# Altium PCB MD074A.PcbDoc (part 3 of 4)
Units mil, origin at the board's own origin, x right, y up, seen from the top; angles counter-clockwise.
Board outline 3224.41 x 4078.74 mil, 4 copper layers (Top Layer, Signal Layer 1, Signal Layer 2, Bottom Layer), stack 61.2 mil thick; 217 components, 121 nets, 624 pads, 901 vias.
Unrouted connection lines stored in the file: 116.
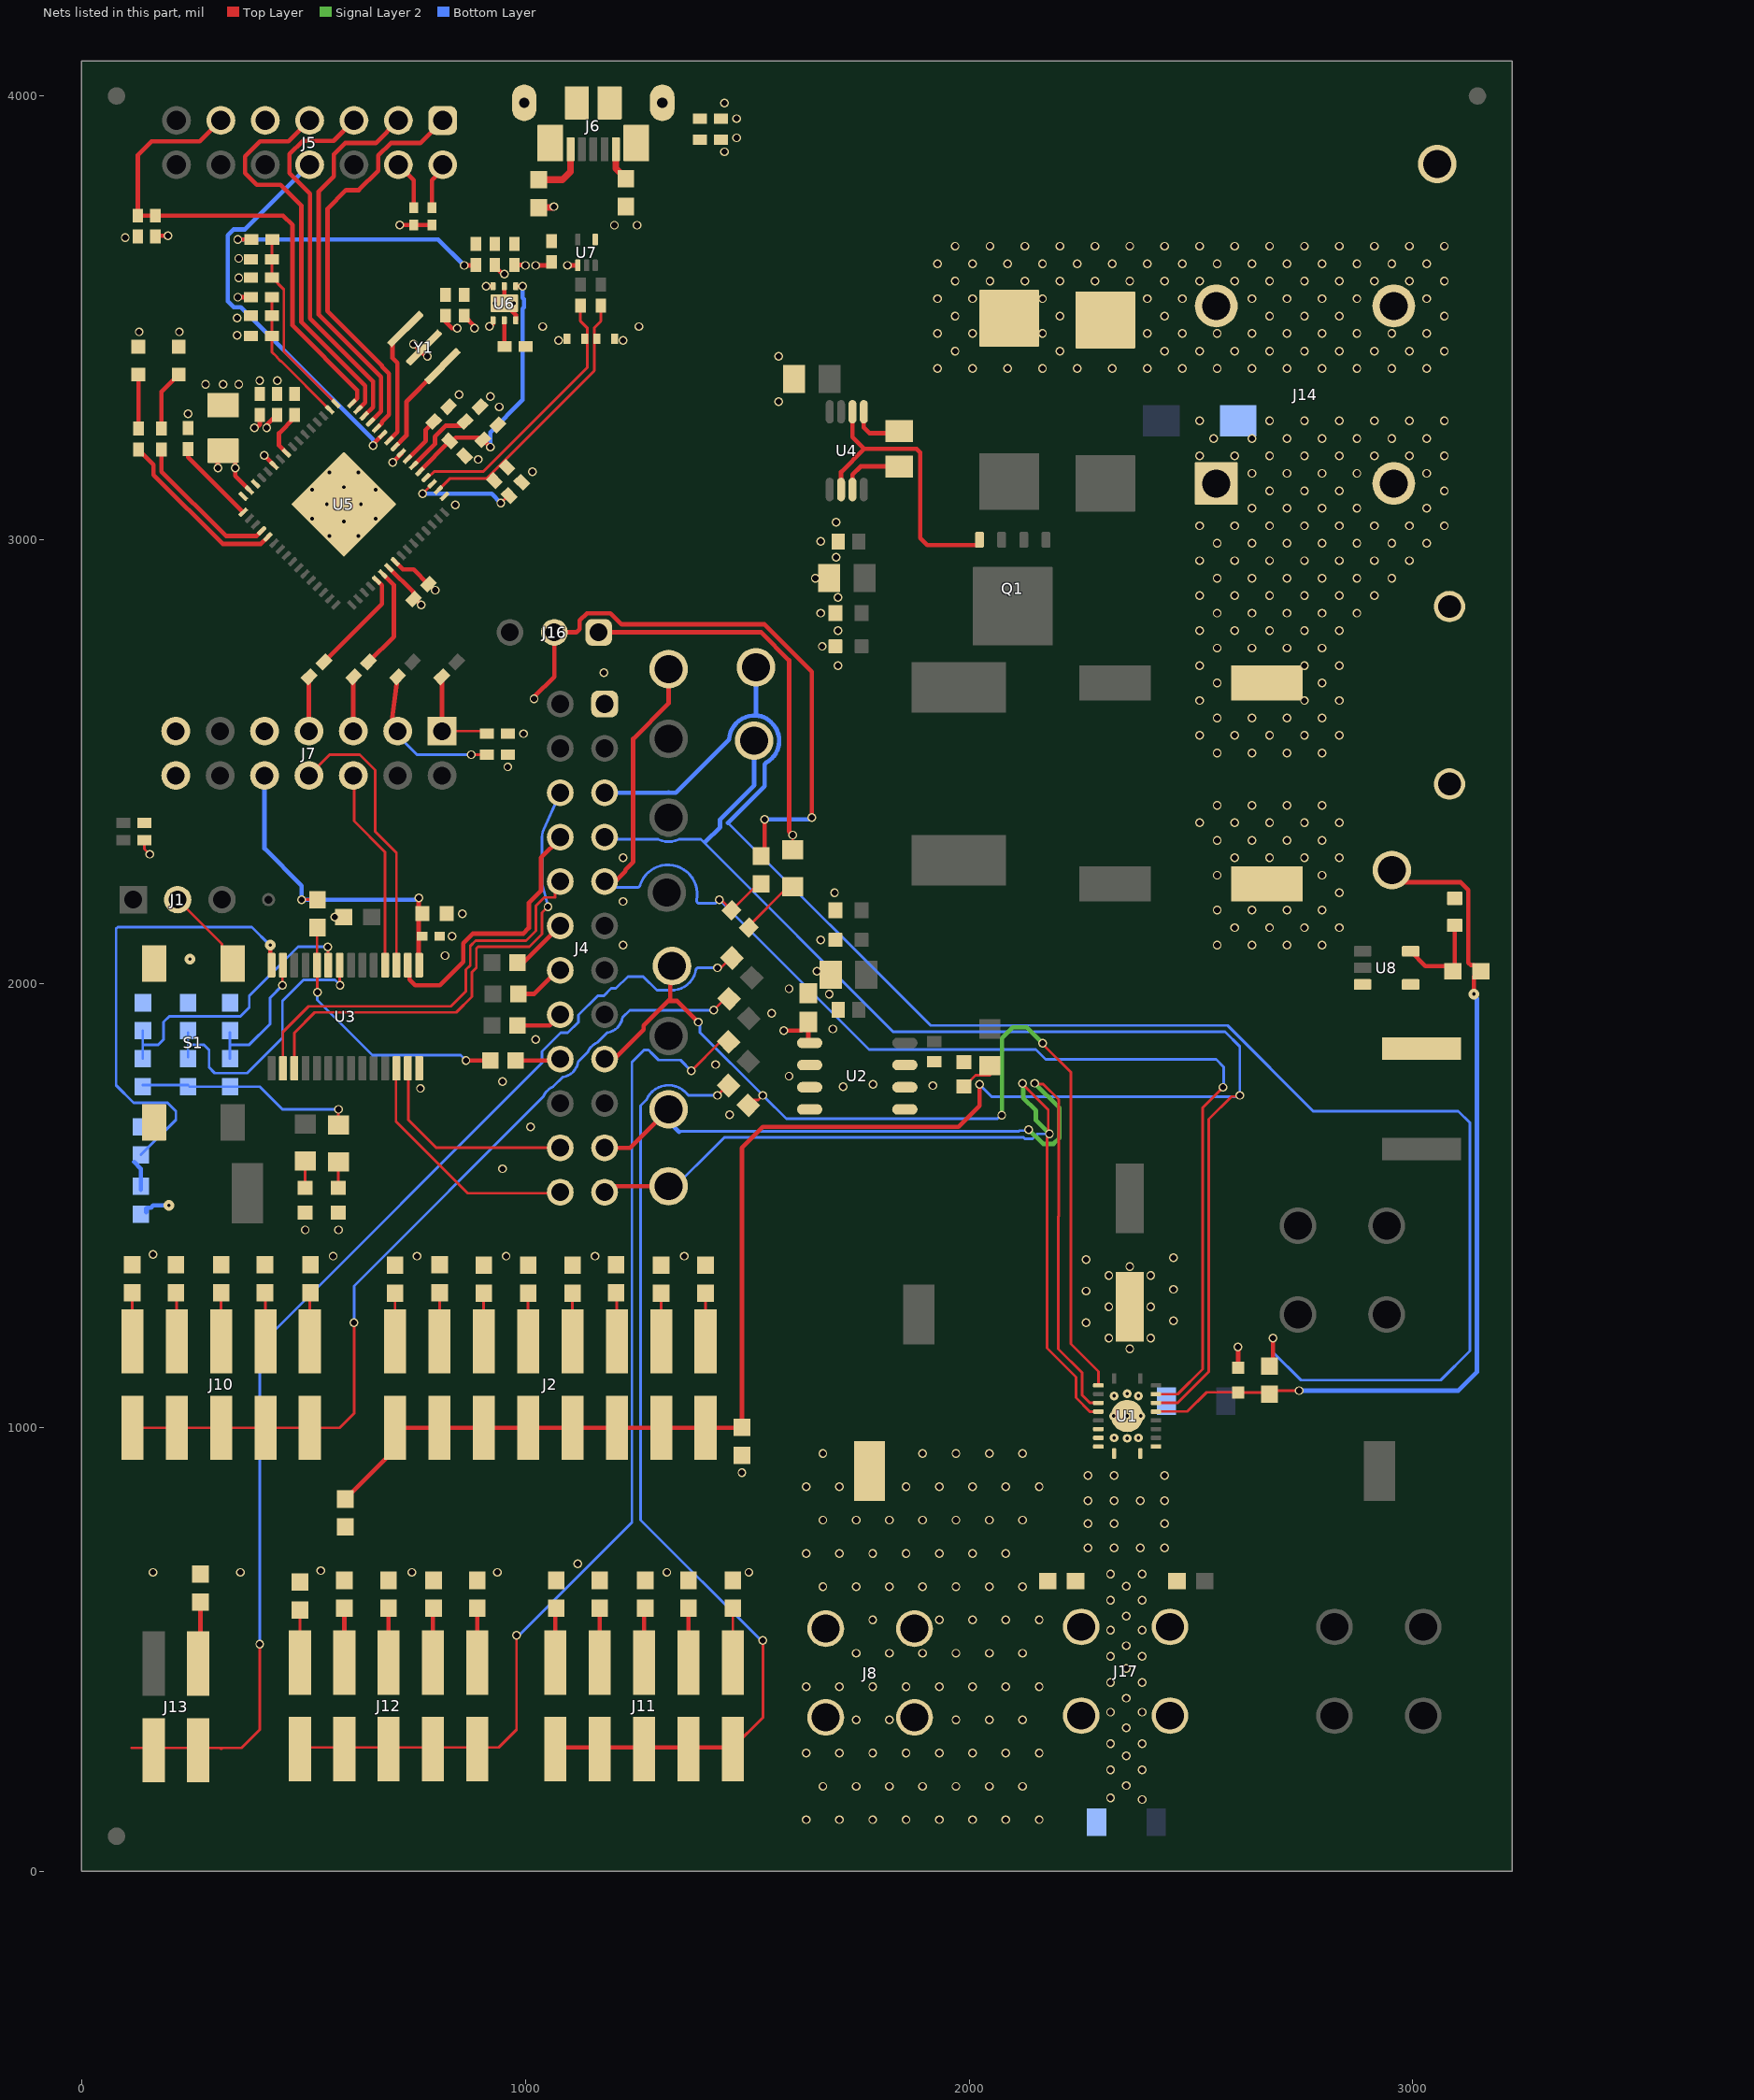
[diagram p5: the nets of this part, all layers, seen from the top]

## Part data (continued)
J3 J8 J9: library part CMP-0055418-2, "Banana Jack Insul Nylon Red, R/A, TH", Color=Red, Current_A=25A, Manufacturer="Cal Test Electronics", Supplier Part Number 1=BKCT3151SP-2-ND, Voltage_V=1kV
J4: library part CMP-0085938-1, "Header, 2.54mm, 12x2, Gold, TH", Alternate Manufacturer="Wurth Elektronik", Alternate PartNumber=61302421121, Color=Black, Current_A=5A, Manufacturer=FCI, Voltage_V=1.5kV
J5: library part CMP-0086014-1, "Header, 2.54mm, 7x2, Gold, TH", Color=Black, Current_A=3A, Manufacturer="Wurth Elektronik", Voltage_V=250V
J6: "Receptacle, USB 2.0, Micro B, 5 Position, R/A, SMT", Color=Black, Current_A=1.8A, Manufacturer=Molex, PartNumber=1051640001, Supplier Part Number 1=WM11263CT-ND, Voltage_V=30V
J7: library part CMP-0002339-2, "Header, 100mil, 7x2, Tin, TH", Alternate Manufacturer="Wurth Elektronik", Alternate PartNumber=61301421121, Color=Black, Current_A=3A, Manufacturer="Sullins Connector Solutions", Supplier Part Number 1=S2012E-07-ND, Voltage_V=1.8kV
J10 J11 J12: library part CMP-0055598-2, "Header, 2.54mm, 5x2, Gold, SMT", Alternate Manufacturer="Wurth Elektronik", Alternate PartNumber=61031021121, Color=Black, Current_A=5.4A, Manufacturer=Samtec, Supplier Part Number 1=SAM8741-ND, Voltage_V=475V
J13: library part CMP-0055559-1, "Header, 2.54mm, 2x2, Gold, SMT", Color=Black, Manufacturer=Samtec, Supplier Part Number 1=TSM-102-01-L-DV-ND, Voltage_V=475V
J14: library part CMP-0086764-1, Current_A=57A, Manufacturer=Wurth, Voltage_V=750V
J15: library part CMP-0075110-1, "1mm Uninsulated Shorting Plug, 10.16mm spacing, TH", Manufacturer=Harwin, Supplier Part Number 1=952-1873-ND
J16: library part CMP-0079327-1, "Header, 2.54mm, 3x1, Gold, TH", Alternate Manufacturer="Wurth Elektronik", Alternate PartNumber=61300311121, Color=Black, Manufacturer=Samtec, Supplier Part Number 1=SAM1038-03-ND
J17: library part CMP-0055417-1, "Banana Jack Insul Nylon Black, R/A, TH", Color=Black, Current_A=25A, Manufacturer="Cal Test Electronics", Supplier Part Number 1=BKCT3151SP-0-ND, Voltage_V=1kV
L1: library part CMP-0063986-1, "Inductor, Shielded Drum Core, Ferrite, 1 uH, 24 A, 0.0012 ohm, SMD", Manufacturer="Wurth Elektronik", Supplier Part Number 1=732-2138-1-ND, Value1="0.0012 ohm", Value2=24A, ValueDisplayed=1uH
L2 L3: library part CMP-0081962-1, "Ferrite Bead, 150 ohm @ 100 MHz, 0.7 A, 0603", Manufacturer=MuRata, Supplier Part Number 1=490-14035-1-ND, Value1="0.35 ohm", Value2=0.7A, ValueDisplayed="150 ohm"
LBL1: library part CMP-0003625-1, "Thermal Transfer Printable Labels, 0.650\" W x 0.200\" H - 10,000 per roll", Manufacturer=Brady, Supplier Part Number 1=97C5133
Logo1: library part CMP-0074844-1
Logo2: library part CMP-0074838-1, "Texas Instrument Corporate Signature"
Logo3: library part CMP-0074847-1, "FCC_disclaimer"
Logo4: library part CMP-0074769-1
Logo5: library part CMP-0074836-1, "IEC 61010-1 Caution Warning"
LOGO6: library part CMP-0074837-2, "IEC 61010-1 Hot Surface Warning", Manufacturer="Texas Instruments"
Q1: library part CMP-0000714-1, "MOSFET, N-CH, 40 V, 100 A, DQJ0008A (VSONP-8)", Alternate Manufacturer=None, Manufacturer="Texas Instruments", Supplier Part Number 1=296-45231-1-ND, Value1=0.004, Value2="47 nC"
R1 R68: library part CMP-0025886-3, "RES, 10 k, 5%, 0.1 W, 0603", Manufacturer="Yageo America", Power_W=100mW, Supplier Part Number 1=311-10KGRCT-ND, TempCo="100 ppm/C", Tolerance_%=5%, Value2=0.1W, Value_Code=10k0, ValueDisplayed=10k
R2 R3 R20: "RES, 330, 5%, 0.1 W, AEC-Q200 Grade 0, 0603", Manufacturer=Vishay-Dale, PartNumber=CRCW0603330RJNEA, Power_W=100mW, Supplier Part Number 1=541-330GCT-ND, TempCo="200 ppm/C", Tolerance_%=5%, Value2=0.1W, Value_Code=330R, ValueDisplayed=330
R4: library part CMP-0082533-1, "RES, 4.99 k, 1%, 0.1 W, 0603", Manufacturer=Vishay-Dale, Power_W=100mW, Supplier Part Number 1=541-3985-1-ND, TempCo="100 ppm/C", Tolerance_%=1%, Value2=0.1W, Value_Code=4k99, ValueDisplayed=4.99k
R5: library part CMP-0023235-5, "RES, 680, 1%, 0.1 W, 0603", Manufacturer=Yageo, Power_W=100mW, Supplier Part Number 1=311-680HRCT-ND, TempCo="100 ppm/C", Tolerance_%=1%, Value2=0.1W, Value_Code=680R, ValueDisplayed=680
R6: library part CMP-0022895-5, "RES, 1.00 k, 1%, 0.1 W, 0603", Manufacturer=Yageo, Power_W=100mW, Supplier Part Number 1=311-1.00KHRCT-ND, TempCo="100 ppm/C", Tolerance_%=1%, Value2=0.1W, Value_Code=1k00, ValueDisplayed=1.00k
R7: library part CMP-0022883-5, "RES, 1.50 k, 1%, 0.1 W, 0603", Manufacturer=Yageo, Power_W=100mW, Supplier Part Number 1=311-1.50KHRCT-ND, TempCo="100 ppm/C", Tolerance_%=1%, Value2=0.1W, Value_Code=1k50, ValueDisplayed=1.50k
R8: library part CMP-0022986-5, "RES, 2.20 k, 1%, 0.1 W, 0603", Manufacturer=Yageo, Power_W=100mW, Supplier Part Number 1=311-2.20KHRCT-ND, TempCo="100 ppm/C", Tolerance_%=1%, Value2=0.1W, Value_Code=2k20, ValueDisplayed=2.20k
R9: library part CMP-0023081-5, "RES, 3.30 k, 1%, 0.1 W, 0603", Manufacturer=Yageo, Power_W=100mW, Supplier Part Number 1=311-3.30KHRCT-ND, TempCo="100 ppm/C", Tolerance_%=1%, Value2=0.1W, Value_Code=3k30, ValueDisplayed=3.30k
R10: library part CMP-0023153-5, "RES, 4.70 k, 1%, 0.1 W, 0603", Manufacturer=Yageo, Power_W=100mW, Supplier Part Number 1=311-4.70KHRCT-ND, TempCo="100 ppm/C", Tolerance_%=1%, Value2=0.1W, Value_Code=4k70, ValueDisplayed=4.70k
R11: library part CMP-0023253-5, "RES, 6.80 k, 1%, 0.1 W, 0603", Manufacturer=Yageo, Power_W=100mW, Supplier Part Number 1=311-6.80KHRCT-ND, TempCo="100 ppm/C", Tolerance_%=1%, Value2=0.1W, Value_Code=6k80, ValueDisplayed=6.80k
R12 R53 R54 R55: library part CMP-0025862-3, "RES, 8.2 k, 5%, 0.1 W, 0603", Manufacturer=Vishay-Dale, Power_W=100mW, Supplier Part Number 1=541-8.2KGCT-ND, TempCo="200 ppm/C", Tolerance_%=5%, Value2=0.1W, Value_Code=8k20, ValueDisplayed=8.2k
R13 R14 R15 R16 R17 R19 R22 R23 R39 R52: library part CMP-0086358-1, "RES, 0, 0%, 0.25 W, AEC-Q200 Grade 0, 0603", Manufacturer=Rohm, Power_W=250mW, Tolerance_%=0%, Value2=0.25W, Value_Code=0000, ValueDisplayed=0
R18: library part CMP-0025925-5, "RES, 47 k, 5%, 0.1 W, 0603", Manufacturer=Yageo, Power_W=100mW, Supplier Part Number 1=311-47KGRCT-ND, TempCo="100 ppm/C", Tolerance_%=5%, Value2=0.1W, Value_Code=47k0, ValueDisplayed=47k
R21 R24 R29 R67 R69 R70 R71 R72: library part CMP-0025886-5, "RES, 10 k, 5%, 0.1 W, 0603", Manufacturer=Yageo, Power_W=100mW, Supplier Part Number 1=311-10KGRCT-ND, TempCo="100 ppm/C", Tolerance_%=5%, Value2=0.1W, Value_Code=10k0, ValueDisplayed=10k
R25 R26 R27 R28: library part CMP-2000-03817-1, Manufacturer="Vishay Dale"
R32: library part CMP-0026190-2, "RES, 240 k, 1%, 0.063 W, AEC-Q200 Grade 0, 0402", Manufacturer=Vishay-Dale, Power_W=63mW, Supplier Part Number 1=541-240KLCT-ND, TempCo="100 ppm/C", Tolerance_%=1%, Value2=0.063W, Value_Code=240k
R33: library part CMP-0026934-3, "RES, 470, 5%, 0.063 W, AEC-Q200 Grade 0, 0402", Manufacturer=Vishay-Dale, Power_W=63mW, Supplier Part Number 1=541-470JCT-ND, TempCo="200 ppm/C", Tolerance_%=5%, Value2=0.063W, Value_Code=470R, ValueDisplayed=470
R34: library part CMP-0026914-3, "RES, 390, 5%, 0.063 W, AEC-Q200 Grade 0, 0402", Manufacturer=Vishay-Dale, Power_W=63mW, Supplier Part Number 1=541-390JCT-ND, TempCo="200 ppm/C", Tolerance_%=5%, Value2=0.063W, Value_Code=390R, ValueDisplayed=390
R35: library part CMP-0026021-3, "RES, 150 k, 1%, 0.063 W, AEC-Q200 Grade 0, 0402", Manufacturer=Vishay-Dale, Power_W=63mW, Supplier Part Number 1=541-150KLCT-ND, TempCo="100 ppm/C", Tolerance_%=1%, Value2=0.063W, Value_Code=150k
R36 R38: library part CMP-0026728-1, "RES, 220 k, 1%, 0.0625 W, 0402", Manufacturer="Yageo America", Power_W=62.5mW, Supplier Part Number 1=311-220KLRCT-ND, TempCo="100 ppm/C", Tolerance_%=1%, Value2=0.0625W, Value_Code=220k
R37 R73: library part CMP-0026935-3, "RES, 47 k, 5%, 0.063 W, AEC-Q200 Grade 0, 0402", Manufacturer=Vishay-Dale, Power_W=63mW, Supplier Part Number 1=541-47KJCT-ND, TempCo="200 ppm/C", Tolerance_%=5%, Value2=0.063W, Value_Code=47k0, ValueDisplayed=47k
R41 R42: library part CMP-0026992-3, "RES, 0, 5%, 0.1 W, AEC-Q200 Grade 0, 0402", Manufacturer=Panasonic, Power_W=100mW, Supplier Part Number 1=P0.0JCT-ND, TempCo="600 ppm/C", Tolerance_%=5%, Value2=0.1W, Value_Code=0000, ValueDisplayed=0
R43 R44: library part CMP-0026888-3, "RES, 27, 5%, 0.063 W, AEC-Q200 Grade 0, 0402", Manufacturer=Vishay-Dale, Power_W=63mW, Supplier Part Number 1=541-27JCT-ND, TempCo="200 ppm/C", Tolerance_%=5%, Value2=0.063W, Value_Code=27R0, ValueDisplayed=27
R45: library part CMP-0026085-3, "RES, 1.40 k, 1%, 0.063 W, AEC-Q200 Grade 0, 0402", Manufacturer=Vishay-Dale, Power_W=63mW, Supplier Part Number 1=541-1.40KLCT-ND, TempCo="100 ppm/C", Tolerance_%=1%, Value2=0.063W, Value_Code=1k40, ValueDisplayed=1.40k
R46: library part CMP-0026859-2, "RES, 1.0 M, 5%, 0.063 W, AEC-Q200 Grade 0, 0402", Manufacturer=Vishay-Dale, Power_W=63mW, Supplier Part Number 1=541-1.0MJCT-ND, TempCo="200 ppm/C", Tolerance_%=5%, Value2=0.063W, Value_Code=1M00, ValueDisplayed=1.0M
R47: library part CMP-0025963-2, "RES, 10.0, 1%, 0.063 W, 0402", Alternate Manufacturer="Wurth Elektronik", Alternate PartNumber=560050310009, Manufacturer=Vishay-Dale, Power_W=63mW, Supplier Part Number 1=541-10.0LCT-ND, TempCo="100 ppm/C", Tolerance_%=1%, Value2=0.063W, Value_Code=10R0, ValueDisplayed=10.0
R48 R49 R50: library part CMP-0025963-2, "RES, 10.0, 1%, 0.063 W, 0402", Manufacturer=Vishay-Dale, Power_W=63mW, Supplier Part Number 1=541-10.0LCT-ND, TempCo="100 ppm/C", Tolerance_%=1%, Value2=0.063W, Value_Code=10R0, ValueDisplayed=10.0
R51: library part CMP-0026907-3, "RES, 33 k, 5%, 0.063 W, AEC-Q200 Grade 0, 0402", Manufacturer=Vishay-Dale, Power_W=63mW, Supplier Part Number 1=541-33KJCT-ND, TempCo="200 ppm/C", Tolerance_%=5%, Value2=0.063W, Value_Code=33k0, ValueDisplayed=33k
R57 R58 R59: library part CMP-0025757-4, "RES, 22 k, 5%, 0.1 W, AEC-Q200 Grade 0, 0603", Manufacturer=Vishay-Dale, Power_W=100mW, Supplier Part Number 1=541-22KGCT-ND, TempCo="200 ppm/C", Tolerance_%=5%, Value2=0.1W, Value_Code=22k0, ValueDisplayed=22k
R61 R62 R63: library part CMP-0022438-1, "RES, 47.0 k, 1%, 0.1 W, AEC-Q200 Grade 0, 0603", Manufacturer=Vishay-Dale, Power_W=100mW, Supplier Part Number 1=541-47.0KHCT-ND, TempCo="100 ppm/C", Tolerance_%=1%, Value2=0.1W, Value_Code=47k0, ValueDisplayed=47.0k
R64 R65 R66: library part CMP-0086261-1, "RES, 100 k, 0.5%, 0.1 W, AEC-Q200 Grade 0, 0603", Manufacturer=Vishay-Dale, Power_W=100mW, TempCo="50 ppm/C", Tolerance_%=0.5%, Value2=0.1W, Value_Code=100k
S1: library part CMP-0002134-3, "Switch, Tactile, SPST-NO, 0.05A, 12V, SMT", CurrentRating_mA=50A, Manufacturer="TE Connectivity", Supplier Part Number 1=450-1129-ND
SH-J1 SH-J2 SH-J3 SH-J4 SH-J5 SH-J6 SH-J7 SH-J8 SH-J9 SH-J10 SH-J11 SH-J12 SH-J13 SH-J14 SH-J15 SH-J16 SH-J17 SH-J19 SH-J20 SH-J21 SH-J22 SH-J23: library part CMP-0003761-2, "Shunt, 2.54mm, Gold, Black", Manufacturer="Wurth Elektronik", Supplier Part Number 1=732-2678-ND
TP1 TP2 TP5 TP6: library part CMP-0055152-1, "Test Point, Miniature, SMT", Manufacturer=Keystone, Supplier Part Number 1=36-5015TR-ND
TP3: library part CMP-0003719-1, "Testpoint", Manufacturer="Texas Instruments"
TP4 TP7 TP8 TP10 TP11 TP12 TP13 TP14 TP15 TP16 TP17: library part CMP-0055147-1, "Test Point, Multipurpose, Red, TH", Color=Red, Manufacturer=Keystone, Supplier Part Number 1=36-5010-ND
TP18: library part CMP-0055147-2, "Test Point, Multipurpose, Red, TH", Color=Red, Manufacturer="Keystone Electronics", Supplier Part Number 1=36-5010-ND
U1: library part CMP-0097829-1, "Automotive H-Bridge Driver with Integrated Current Sense and Diagnostics", Manufacturer="Texas Instruments", Max Supply Voltage=35V, Min Supply Voltage=4.5V, Nominal Supply Current=3mA, Operating Temperature Range="-40°C to +150°C", Switching Frequency=25kHz
U2: library part CMP-0070570-1, "Ultra-Low Quiescent Current Voltage Regulator, 8-pin Narrow SOIC, Pb-Free", Manufacturer="Texas Instruments", PackageTopMarking=NSZXTT*LM903*6M-3, PowerWise=N
U3: library part CMP-0365-00685-2, "16 MHz Mixed Signal Microcontroller with 16 KB Flash, 512 B SRAM and 24 GPIOs, -40 to 85 degC, 28-pin SOP (PW), Green (RoHS & no Sb/Br)", Frequency(MHz)=16, Manufacturer="Texas Instruments", Temp Sensor=Yes
U4: library part CMP-0076397-2, "Zero Iq Reverse Polarity Protection Smart Diode Controller, DGK0008A (VSSOP-8)", Alternate Manufacturer="Texas Instruments"
U5: "16-Bit Ultra-Low-Power Microcontroller, 128KB Flash, 8KB RAM, USB, 12Bit ADC, 2 USCIs, 32Bit HW MPY, RGC0064B (VQFN-64)", Alternate Manufacturer="Texas Instruments", Alternate PartNumber=MSP430F5528IRGCR, Frequency(MHz)=25, Operating Temperature Range="-40 to 85 C", PartNumber=MSP430F5528IRGCT, Rating=Catalog, Temp Sensor=Yes
U6: library part CMP-0036330-5, "Single Output High PSRR LDO, 500 mA, Fixed 3.3 V Output, 2.7 to 6.5 V Input, with Low IQ, 6-pin SON (DRV), -40 to 125 degC, Green (RoHS & no Sb/Br)", Manufacturer="Texas Instruments"
U7: library part CMP-0043096-2, "Low-Capacitance + / - 15 kV ESD-Protection Array for High-Speed Data Interfaces, 2 Channels, -40 to +85 degC, 5-pin SOT (DRL), Green (RoHS & no Sb/Br)", Breakdown Voltage(Min)(V)=11, IO Capacitance(Typ)(pF)=1.5, IO Leakage Current(nA)=1, Manufacturer="Texas Instruments"
U8: library part CMP-0077329-2, "Automotive High-Voltage Ultra-Low IQ Low-Dropout Regulator/Fixed 5-V Output Voltage, DBV0005A (SOT-23-5)", Alternate Manufacturer="Texas Instruments"
Y1: library part CMP-0085483-1, "Oscillator, 4 MHz, 700 ppm, 39 pF, SMD", Frequency_Fixed=4MHz, Frequency Tolerance="700 ppm", Load Capacitance="39 pF", Manufacturer=MuRata
ZZ1: library part CMP-0003616-3
ZZ2: library part CMP-0077236-1
ZZ3: library part CMP-0077237-1
ZZ4: library part CMP-0077238-1

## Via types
v1: diameter 19.68, hole 13.78, Top Layer to Bottom Layer, tented both sides, 869 vias
v2: diameter 19.68, hole 7.87, Top Layer to Bottom Layer, 14 vias
v3: diameter 19.68, hole 7.87, Top Layer to Bottom Layer, tented both sides, 9 vias
v4: diameter 19.68, hole 13.78, Top Layer to Bottom Layer, tented bottom, 5 vias
v5: diameter 24, hole 8, Top Layer to Bottom Layer, tented both sides, 4 vias

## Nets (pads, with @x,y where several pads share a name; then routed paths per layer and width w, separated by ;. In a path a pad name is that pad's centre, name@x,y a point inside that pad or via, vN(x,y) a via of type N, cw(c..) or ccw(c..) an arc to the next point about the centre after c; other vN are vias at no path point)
3V3: C5.1 D2.2 J16.1 U2.1 | length 992.6
  Top Layer w6: D2.2@1602.36,2303.15 v1(1602.36,2334.65)
  Top Layer w10: J16.1@1165.35,2791.34 1531.5,2791.34 1594.49,2728.35 1594.49,2342.52 v1(1602.36,2334.65) ; v1(1582.68,1893.7) 1622.05,1893.7 C5.1@1637.8,1909.45 ; U2.1@1637.8,1866.14 C5.1@1637.8,1909.45 ; C5.1@1637.8,1913.39 C5.1@1637.8,1909.45
3V3_MCU: C17.1 C18.1 D7.2 J7.10 J16.2 R1.2 R18.2 R21.1 R24.1 R67.1 R68.1 R69.1 R73.2 U3.1 | length 2753
  Top Layer w6: R73.2@137.8,2322.83 141.73,2318.9 141.73,2303.15 v1(153.54,2291.34) ; v1(496.06,2188.98) R68.1@531.5,2188.98 ; v1(570.87,2149.61) R18.2@590.55,2149.61 R18.2@602.36,2149.61 ; D7.2@578.74,1681.1 v1(578.74,1716.54) ; R1.2@1527.56,2287.4 R1.2@1531.5,2291.34
  Top Layer w10: U3.1@759.84,2035.43 v1(759.84,2192.91) ; v1@1019.68,2645.67 1065.35,2691.34 J16.2@1065.35,2791.34 1115.02,2791.34 1122.36,2798.68 1122.36,2817.97 1138.72,2834.33 1191.98,2834.33 1217.1,2809.21 1538.9,2809.21 1645.67,2702.44 v4(1645.67,2374.02) ; R1.2@1531.5,2287.4 R1.2@1531.5,2291.34 ; R1.2@1535.43,2291.34 1539.37,2295.28 v4(1539.37,2370.08)
  Bottom Layer w6: R21.1@137.8,1771.65 R67.1@240.16,1771.65 ; R67.1@244.09,1767.72 R69.1@334.65,1767.72 401.57,1767.72 452.76,1716.54 v1(578.74,1716.54)
  Bottom Layer w10: R24.1@145.67,1484.25 145.67,1493.11 147.56,1495 156.42,1495 161.42,1500 v5(196.85,1500) ; J7.10@412.4,2468.8 412.4,2304.14 496.06,2220.47 v1(496.06,2188.98) 751.97,2188.98 v1(759.84,2192.91) ; v4(1539.37,2370.08) 1641.73,2370.08 v4(1645.67,2374.02)
  other v1: 1019.68,2641.73
+5: C40.2 R19.2 U8.5 | length 204.8
  Top Layer w10: U8.5@2995.08,2072.83 3028.54,2039.37 3094.49,2039.37 C40.2@3094.49,2130.91
DRVOFF: J4.23 TP17.1 U1.5 | length 2028.8
  Top Layer w6: v1(2120.65,1774.72) 2120.65,1773.65 2178.48,1715.82 2178.48,1664.04 v1(2181.1,1661.42) 2181.1,1657.71 2175.63,1652.24 2175.63,1178.7 2240.91,1113.43 2240.91,1066.82 2272.3,1035.43 U1.5@2291.34,1035.43
  Top Layer w10: J4.23@1185.04,1531.5 1196.85,1543.31 TP17.1@1322.83,1543.31
  Signal Layer 2 w10: v1(2120.65,1774.72) 2122.05,1773.33 2122.05,1742.11 2150.65,1713.51 2150.65,1691.87 v1(2181.1,1661.42)
  Bottom Layer w6: TP17.1@1318.9,1523.62 1448.82,1653.54 2122.51,1653.54 2125.86,1650.19 2143.02,1650.19 2154.25,1661.42 v1(2181.1,1661.42)
DRVOFF_MCU: J4.24 U3.26 | length 557.4
  Top Layer w6: U3.26@709.65,1809.06 708.66,1808.07 708.66,1688.98 870.08,1527.56 J4.24@1078.74,1527.56
EN/IN1: J4.21 TP16.1 U1.4 | length 2052.1
  Top Layer w6: v1(2148.2,1775.4) 2150.19,1773.41 2167.04,1773.41 2201.82,1738.63 2201.82,1475.54 2201.44,1475.16 2201.44,1176.58 2254.78,1123.24 2254.78,1072.57 2272.03,1055.32 2273.58,1055.32 2273.78,1055.12 U1.4@2291.34,1055.12
  Top Layer w10: J4.21@1192.91,1629.92 1236.22,1629.92 TP16.1@1322.83,1716.54
  Signal Layer 2 w10: v1(2134.44,1670.91) 2166.65,1638.7 2190.51,1638.7 2203.82,1652.01 2203.82,1719.9 2148.32,1775.4 v1(2148.2,1775.4)
  Bottom Layer w6: 1346.47,1666.85 1442.51,1666.85 1443.07,1667.42 2112.6,1667.42 2113.73,1668.55 2132.08,1668.55 v1(2134.44,1670.91)
  Bottom Layer w10: TP16.1@1322.83,1716.54 1322.83,1688.98 1346.46,1665.35
EN/IN1_MCU: J4.22 U3.27 | length 485.2
  Top Layer w6: U3.27@735.24,1809.06 736.22,1808.07 736.22,1692.91 799.21,1629.92 J4.22@1078.74,1629.92
EZFET_AVBUS: C21.1 R32.1 R35.2 U5.1 | length 426.5
  Top Layer w6: R32.1@430.05,3673.49 429.23,3672.67 C21.1@429.23,3590.85 429.23,3590.69 455.96,3563.95 455.96,3424.05 U5.1@573.09,3306.92
EZFET_AVCC2ADC: C24.1 R36.1 R38.2 U5.2 | length 471.7
  Top Layer w6: R36.1@429.34,3546.49 429.34,3422.83 ; U5.2@559.17,3293 449.78,3402.39 448.68,3402.39 440.55,3410.51 440.55,3411.62 429.34,3422.83 ; 429.34,3422.83 R38.2@429.34,3504.74 429.34,3422.83
EZFET_D_N: C49.1 R43.2 U5.52 | length 654
  Top Layer w6.3: U5.52@776.31,3139.89 780.77,3139.89 794.69,3153.8 905.5,3153.8 1139.24,3387.55 1139.24,3477.56 ; R43.2@1124.38,3527.86 1124.38,3492.43 ; 1124.38,3492.43 1139.24,3477.56 ; 1124.38,3492.43 1139.24,3477.56 ; 1124.38,3492.43 1139.24,3477.56
EZFET_D_P: C50.1 R44.2 R45.1 R46.2 U5.50 | length 646.1
  Top Layer w6.3: U5.50@804.15,3112.05 829.61,3137.51 912.25,3137.51 919.73,3144.98 ; R45.1@930.18,3133.04 930.18,3134.53 919.73,3144.98 ; R46.2@948.86,3172.86 R46.2@958.65,3163.06 ; R44.2@1170.41,3527.86 1170.41,3492.43 1155.54,3477.56 1155.54,3380.8 919.73,3144.98
EZFET_LED0: R33.2 U5.20 | length 340.1
  Top Layer w10: R33.2@180.25,3202.99 180.25,3153.76 325.53,3008.49 394.36,3008.49 U5.20@406.06,3020.18
EZFET_LED1: R34.2 U5.21 | length 399.3
  Top Layer w10: R34.2@128.28,3202.99 162.37,3168.9 162.37,3146.36 318.12,2990.61 404,2990.61 419.64,3006.26 U5.21@419.98,3006.26
EZFET_PUR: R45.2 U5.51 | length 244.5
  Top Layer w6: v1(768.35,3103.56) 790.23,3125.43 U5.51@790.23,3125.97 ; v1(944.88,3082.68) R45.2@964.57,3102.36
  Bottom Layer w10: v1(768.35,3103.56) 924,3103.56 v1(944.88,3082.68)
EZFET_RST: C23.1 J5.11 R37.1 U5.64 | length 1180.5
  Top Layer w10: J5.11@314.02,3944.87 266.58,3897.43 157.42,3897.43 127.1,3867.11 C23.1@127.1,3730.27 R37.1@166.47,3730.27 454.13,3730.27 475.44,3708.96 475.44,3482.58 621.17,3336.85 621.17,3318.81 U5.64@609.28,3306.92
EZFET_TCK: J5.7 U5.63 | length 899.5
  Top Layer w10: J5.7@514.02,3944.87 466.58,3897.43 402.44,3897.43 368.66,3863.65 368.66,3826.08 395.23,3799.51 448.64,3799.51 495.12,3753.03 495.12,3490.74 639.04,3346.82 639.04,3308.84 U5.63@623.2,3293
EZFET_TDI: J5.3 U5.61 | length 862.4
  Top Layer w10: U5.61@651.04,3265.16 674.79,3288.91 674.79,3366.75 534.49,3507.04 534.49,3785.02 568.66,3819.2 568.66,3868.48 594.07,3893.88 663.03,3893.88 J5.3@714.02,3944.87
EZFET_TDO: J5.1 U5.60 | length 925.4
  Top Layer w10: U5.60@664.96,3251.24 676.84,3263.13 676.84,3265.69 692.66,3281.51 692.66,3374.15 676.84,3389.97 676.84,3392.53 554.18,3515.2 554.18,3745.43 596.44,3787.7 624.65,3787.7 668.66,3831.71 668.66,3865.63 696.91,3893.88 763.03,3893.88 J5.1@814.02,3944.87
EZFET_TEST: J5.8 U5.59 | length 902.9
  Top Layer w10: v1(657.05,3212.42) 657.05,3215.49 U5.59@678.88,3237.32
  Bottom Layer w10: J5.8@514.02,3844.87 368.35,3699.2 342.76,3699.2 329.45,3685.89 329.45,3537.08 342.76,3523.78 358.74,3523.78 657.05,3225.46 v1(657.05,3212.42)
EZFET_TMS: J5.5 U5.62 | length 852.8
  Top Layer w10: J5.5@614.02,3944.87 568.03,3898.88 498.68,3898.88 468.66,3868.86 468.66,3826.08 514.81,3779.94 514.81,3498.89 656.91,3356.78 656.91,3298.88 U5.62@637.12,3279.08
EZFET_UARTRXD: R49.1 U5.38 | length 232.1
  Top Layer w10: R49.1@646.72,2724.71 703.93,2781.92 703.93,2897.69 U5.38@678.88,2922.74
EZFET_UARTTXD: R50.1 U5.37 | length 243.1
  Top Layer w10: R50.1@546.45,2724.65 676.84,2855.05 676.84,2896.94 U5.37@664.96,2908.82
EZFET_USB_Shield: C44.1 J6.6 J6.7 J6.8 J6.9 J6.10 J6.11 R51.2
EZFET_V18: C25.1 U5.55 | length 109.2
  Top Layer w10: U5.55@734.55,3181.64 775.56,3222.57 775.56,3248.27 C25.1@793.66,3266.36
EZFET_VBUS: C19.1 C20.1 C28.1 C29.1 C30.1 C45.1 L2.2 R32.2 U5.53 U6.4 U6.6 U7.1 | length 1371.4
  Top Layer w6: U6.6@927.22,3571.21 U6.6@927.22,3571.21 ; v1@948.82,3598.43 v1(952.76,3598.43) ; U6.4@978.4,3571.21 U6.4@978.4,3571.21 ; v1@999.02,3619.09 v1(1000,3618.11) ; U7.1@1117.35,3619.11 U7.1@1118.24,3618.22
  Top Layer w10: v1(352.17,3676.49) R32.2@382.43,3676.49 ; U5.53@762.39,3153.8 C20.1@829.81,3222.57 835.42,3222.57 843.18,3230.33 899.43,3230.33 921.1,3208.66 v1(921.26,3208.66) ; v1(862.2,3618.11) C28.1@889.76,3618.11 ; v1(911.47,3571.17) U6.6@927.22,3571.21 ; C29.1@933.07,3614.17 v1@948.82,3598.43 ; C30.1@975.35,3619.09 v1@999.02,3619.09 ; U6.4@978.4,3571.21 v1(994.15,3571.17) ; v1@1019.68,3618.11 1051.18,3618.11 C45.1@1059.06,3625.98 ; v1(1095.09,3618.22) 1116.45,3618.22 U7.1@1117.35,3619.11
  Top Layer w15: L2.2@1030.48,3748.44 1062.22,3748.44 v1(1064.42,3750.65)
  Bottom Layer w10: v1(352.17,3676.49) 803.83,3676.49 v1(862.2,3618.11) ; v1(921.26,3208.66) 921.26,3242.12 994.15,3315.01 994.15,3520.38 997.18,3523.41 997.18,3542.23 994.15,3545.26 v1(994.15,3571.17)
  other v1: 1023.62,3618.11
EZFET_VCC: C31.1 C33.1 C34.1 C35.1 C36.1 C37.1 J7.9 R36.2 R37.2 R41.1 R42.1 U5.11 U5.15 U5.40 U6.1 | length 587.8
  Top Layer w6: C34.1@342.52,3188.98 C34.1@346.46,3185.04 ; C37.1@781.65,2899.89 783.6,2899.89 v1(797.12,2886.37)
  Top Layer w10: R37.2@166.47,3683.02 168.44,3684.99 v1(194.88,3684.99) ; v1(307.09,3161.42) C34.1@307.09,3196.85 ; C34.1@346.46,3185.04 v1(346.46,3161.42) 346.46,3143.81 U5.15@378.22,3112.05 ; v1(352.17,3546.49) R36.2@382.09,3546.49 ; v1(389.76,3251.97) 393.7,3251.97 401.77,3260.04 C36.1@401.77,3281.51 ; v1(411.82,3189.8) U5.11@433.89,3167.72 ; v1(417.32,3251.97) 417.32,3258.28 C35.1@440.55,3281.51 ; U5.40@706.72,2950.58 724,2933.29 748.24,2933.29 C37.1@781.65,2899.89 ; v1(717.03,3708.96) 743.65,3708.96 746.06,3706.55 R41.1@748.47,3708.96 R42.1@789.85,3708.96 ; C33.1@820.1,3504.94 820.1,3490.92 834.65,3476.38 v1(846.46,3476.38) ; C31.1@862.2,3504.74 885.83,3481.12 v1(885.83,3476.38) ; v1(919.33,3480.56) 927.22,3486.19 U6.1@927.22,3494.44
EZFET_Vcore: C26.1 U5.17 | length 194.6
  Top Layer w10: C26.1@245.21,3202.99 240.16,3197.94 240.16,3186.08 U5.17@364.3,3061.94
EZFET_VREF: C22.1 U5.9 | length 107.6
  Top Layer w10: U5.9@461.73,3195.56 444.9,3212.4 444.9,3240.09 480.31,3275.5 C22.1@480.31,3281.51
EZFET_VUSB: C27.1 U5.54 | length 260.3
  Top Layer w10: U5.54@748.47,3167.72 796.33,3215.5 796.33,3232.46 820.57,3256.71 ; C27.1@864.49,3266.36 C27.1@864.49,3256.71 ; 820.57,3256.71 C27.1@864.49,3256.71 ; 820.57,3256.71 C27.1@864.49,3256.71 ; 820.57,3256.71 C27.1@864.49,3256.71
EZFET_XT2IN: U5.57 Y1.1 | length 201.2
  Top Layer w10: U5.57@706.72,3209.48 732.28,3235.05 732.28,3311.02 Y1.1@795.28,3374.02
EZFET_XT2OUT: U5.58 Y1.3 | length 234
  Top Layer w10: U5.58@692.8,3223.4 711.95,3242.55 711.95,3398.29 700.79,3409.45 Y1.3@700.79,3444.88
GND: C1.2 C2.2 C4.2 C5.2 C6.1 C7.1 C8.1 C9.2 C10.2 C11.1 C12.1 C13.1 C14.2 C15.2 C16.2 C17.2 C18.2 C19.2 C20.2 C21.2 C22.2 C23.2 C24.2 C25.2 C26.2 C27.2 C28.2 C29.2 C30.2 C31.2 C32.2 C33.2 C34.2 C35.2 C36.2 C37.2 C38.1 C39.1 C40.1 C41.2 C42.1 C43.2 C44.2 C45.2 C47.1 C48.1 C49.2 C50.2 C52.2 C53.2 D4.1 D5.1 D6.1 J4.1 J5.9 J7.13 J7.14 J14.1 J15.1 J15.2 J17.1 L3.2 R2.1 R4.1 R5.1 R6.1 R7.1 R8.1 R9.1 R10.1 R11.1 R12.1 R13.2 R15.2 R17.2 R20.1 R23.2 R29.2 R35.1 R38.1 R46.1 R51.1 R53.1 R54.1 R55.1 R57.1 R58.1 R59.1 R61.1 R62.1 R63.1 R64.1 R65.1 R66.1 R70.2 R71.2 R72.2 S1.3 S1.4 U1.9 U1.10 U1.11 U1.12 U1.21 U2.2 U2.3 U2.4 U2.5 U2.6 U2.7 U3.28 U5.14 U5.16 U5.39 U5.49 U5.56 U5.65 U6.3 U6.5 U6.7@952.81,3532.82 U7.4 U8.3 U8.4 Y1.2 | length 319.7
  Top Layer w6: C37.2@748.24,2866.48 C37.2@752.41,2866.48 ; v1@775.59,3413.39 v1(779.53,3413.39)
  Top Layer w10: U5.39@692.8,2936.66 748.24,2881.22 C37.2@748.24,2866.48 ; v1(700.89,3173.99) 720.63,3193.73 U5.56@720.63,3195.56 ; v1(748.03,3440.94) v1@775.59,3413.39 ; C37.2@752.41,2866.48 v1(765.75,2853.14) ; U6.5@952.81,3571.21 U6.7@952.81,3532.82 978.4,3507.23 U6.3@978.4,3494.44 ; J4.1@1177.17,2631.58 J4.1@1177.32,2631.73 ; C41.2@2606.3,1133.86 v1@2606.3,1177.17
  other v1: 2389.76,161.42 2318.9,165.35 2354.33,192.91 2318.9,228.35 2389.76,228.35 2354.33,259.84 2318.9,287.4 2389.76,287.4 2354.33,322.83 2318.9,358.27 2389.76,358.27 2354.33,389.76 2318.9,425.2 2389.76,425.2 2354.33,456.69 2318.9,484.25 2389.76,484.25 2354.33,507.87 2318.9,543.31 2389.76,543.31 2354.33,574.8 2318.9,610.24 2389.76,610.24 2354.33,641.73 2318.9,669.29 2389.76,669.29 161.42,673.23 358.27,673.23 744.09,673.23 937.01,673.23 1318.9,673.23 1503.94,673.23 539.37,677.17 1118.11,692.91 2267.72,728.35 2326.77,728.35 2385.83,728.35 2440.95,728.35 2267.72,783.46 2326.77,783.46 2440.95,783.46 2267.72,834.65 2326.77,834.65 2385.83,834.65 2440.95,834.65 2267.72,891.73 2326.77,891.73 2440.95,891.73 1488.19,897.64 2362.2,1177.17 2606.3,1181.1 2314.96,1200.79 2409.45,1200.79 2263.78,1236.22 2460.63,1240.16 2314.96,1271.65 2409.45,1271.65 2263.78,1307.09 2460.63,1311.02 2314.96,1342.52 2409.45,1342.52 2362.2,1362.2 2263.78,1377.95 2460.63,1381.89 566.93,1385.83 755.91,1385.83 956.69,1385.83 1157.48,1385.83 1358.27,1385.83 161.42,1389.76 503.94,1444.88 578.74,1444.88 948.82,1582.68 1011.81,1677.17 1460.63,1704.72 763.78,1763.78 1716.54,1767.72 1918.72,1770.15 1783.46,1772.68 948.82,1779.53 1594.49,1791.34 1429.13,1817.56 1023.62,1874.02 1692.91,1897.64 1555.12,1933.07 1685.04,1976.38 1594.49,1988.19 1657.48,2027.56 818.9,2062.99 1220.47,2086.61 2559.06,2086.61 2637.8,2086.61 2716.54,2086.61 2795.28,2086.61 1665.35,2098.43 834.65,2106.3 2598.43,2125.98 2677.17,2125.98 2755.91,2125.98 2834.65,2125.98 858.27,2157.48 2559.06,2165.35 2637.8,2165.35 2716.54,2165.35 2795.28,2165.35 1220.47,2185.04 1696.85,2204.72 2834.65,2204.72 2559.06,2244.09 2795.28,2244.09 1220.47,2283.46 2598.43,2283.46 2677.17,2283.46 2755.91,2283.46 2834.65,2283.46 2559.06,2322.83 2637.8,2322.83 2716.54,2322.83 2795.28,2322.83 2519.68,2362.2 2598.43,2362.2 2677.17,2362.2 2755.91,2362.2 2834.65,2362.2 2559.06,2401.57 2637.8,2401.57 2716.54,2401.57 2795.28,2401.57 960.63,2488.19 2559.06,2519.68 2637.8,2519.68 2716.54,2519.68 2795.28,2519.68 2519.68,2559.06 2598.43,2559.06 2677.17,2559.06 2755.91,2559.06 2834.65,2559.06 996.06,2562.99 2559.06,2598.43 2637.8,2598.43 2716.54,2598.43 2795.28,2598.43 2519.68,2637.8 2755.91,2637.8 2834.65,2637.8 2559.06,2677.17 2795.28,2677.17 1704.72,2716.54 2519.68,2716.54 2755.91,2716.54 2834.65,2716.54 2559.06,2755.91 2637.8,2755.91 2716.54,2755.91 2795.28,2755.91 1669.29,2759.84 1704.72,2795.28 2519.68,2795.28 2598.43,2795.28 2677.17,2795.28 2755.91,2795.28 2834.65,2795.28 1665.35,2834.65 2559.06,2834.65 2637.8,2834.65 2716.54,2834.65 2795.28,2834.65 2874.02,2834.65 1704.72,2870.08 2519.68,2874.02 2598.43,2874.02 2677.17,2874.02 2755.91,2874.02 2834.65,2874.02 2913.39,2874.02 1653.54,2913.39 2559.06,2913.39 2637.8,2913.39 2716.54,2913.39 2795.28,2913.39 2874.02,2913.39 2952.76,2913.39 2519.68,2952.76 2598.43,2952.76 2677.17,2952.76 2755.91,2952.76 2834.65,2952.76 2913.39,2952.76 2992.13,2952.76 1700.79,2960.63 2559.06,2992.13 2637.8,2992.13 2716.54,2992.13 2795.28,2992.13 2874.02,2992.13 2952.76,2992.13 3031.5,2992.13 1665.35,2996.06 2519.68,3031.5 2598.43,3031.5 2677.17,3031.5 2755.91,3031.5 2834.65,3031.5 2913.39,3031.5 2992.13,3031.5 3070.87,3031.5 1700.79,3039.37 2637.8,3070.87 2716.54,3070.87 2795.28,3070.87 2874.02,3070.87 3031.5,3070.87 842.52,3078.74 2677.17,3110.24 2755.91,3110.24 2834.65,3110.24 3070.87,3110.24 2637.8,3149.61 2716.54,3149.61 2795.28,3149.61 2874.02,3149.61 3031.5,3149.61 1015.75,3153.54 893.7,3181.1 2519.68,3188.98 2598.43,3188.98 2677.17,3188.98 2755.91,3188.98 2834.65,3188.98 2913.39,3188.98 2992.13,3188.98 3070.87,3188.98 2551.18,3228.35 2637.8,3228.35 2716.54,3228.35 2795.28,3228.35 2874.02,3228.35 2952.76,3228.35 3031.5,3228.35 2519.68,3267.72 2677.17,3267.72 2755.91,3267.72 2834.65,3267.72 2913.39,3267.72 2992.13,3267.72 3070.87,3267.72 240.16,3283.46 940.94,3299.21 1570.87,3311.02 921.26,3322.83 850.39,3326.77 279.53,3350.39 318.9,3350.39 354.33,3350.39 401.57,3358.27 440.94,3358.27 1570.87,3413.39 1074.8,3448.82 1220.47,3448.82 350.39,3460.63 129.92,3468.5 220.47,3468.5 1039.37,3480.31 1255.91,3480.31 350.39,3499.99 354.33,3590.55 354.33,3633.86 98.43,3681.1 1200.79,3708.66 1251.97,3708.66 1448.82,3874.02 1476.38,3905.51 1476.38,3948.82 1448.82,3984.25
  other v2: 558.33,3008.49 624.03,3008.49 591.18,3041.34 519.64,3047.18 662.73,3047.18 552.49,3080.03 629.88,3080.03 519.64,3112.88 662.73,3112.88 591.18,3118.73 558.33,3151.58 624.03,3151.58 931.16,3532.82 974.47,3532.82
  other v3: 2356.3,975.39 2326.77,976.38 2381.89,976.38 2325.79,1025.59 2356.3,1025.59 2386.81,1025.59 2326.77,1070.87 2381.89,1070.87 2356.3,1075.79
  other v4: 1177.17,2700.79
  other v5: 244.09,2055.12
ID0: R24.2 R29.1 U3.14 | length 1096.7
  Top Layer w10: U3.14@425.2,2066.93 v5(425.2,2086.61)
  Bottom Layer w6: R29.1@133.86,1614.17 212.6,1692.91 212.6,1712.6 193.87,1731.33 117.59,1731.33 78,1770.92 78,2123.83 81.51,2127.34 383.42,2127.34 v5@424.15,2086.61
  Bottom Layer w10: R29.1@118.6,1597.93 133.86,1582.68 R24.2@133.86,1543.31 R24.2@133.86,1535.43 ; v5@424.15,2086.61 v5(425.2,2086.61)
ID1: R21.2 R70.1 U3.9 | length 656.6
  Top Layer w6: v1(555.12,2082.68) 555.12,2047.24 U3.9@559.06,2043.31
  Bottom Layer w6: R21.2@137.8,1830.71 137.8,1862.2 ; R70.1@137.8,1893.7 137.8,1862.2 ; v1(555.12,2082.68) 488.19,2082.68 421.26,2015.75 ; 137.8,1862.2 173.23,1862.2 185.04,1874.02 185.04,1913.39 197.79,1926.13 357.85,1926.13 377.95,1946.24 377.95,1972.44 417.32,2011.81 ; 417.32,2011.81 421.26,2015.75 ; 417.32,2011.81 421.26,2015.75
ID2: R67.2 R71.1 U3.8 | length 636.9
  Top Layer w6: U3.8@581.69,2041.34 581.69,1993.11 v1@582.68,1992.13
  Bottom Layer w6: R67.2@240.16,1834.65 240.16,1862.2 ; R71.1@240.16,1889.76 240.16,1862.2 ; v1(582.68,1996.06) 570.87,2007.87 500,2007.87 452.76,1960.63 452.76,1877.95 373.08,1798.28 300.15,1798.28 287.4,1811.02 287.4,1850.39 275.59,1862.2 240.16,1862.2
ID3: R69.2 R72.1 U3.13 | length 314.4
  Top Layer w6: v1(452.76,1996.06) U3.13@452.76,2043.31
  Bottom Layer w6: R69.2@334.65,1830.71 334.65,1862.2 ; R72.1@334.65,1889.76 334.65,1862.2 ; v1(452.76,1996.06) 425.2,1968.5 425.2,1909.45 377.95,1862.2 334.65,1862.2
IPROPI: C42.2 C53.1 J2.2 J2.4 J2.6 J2.8 J2.10 J2.12 J2.14 J2.16 J4.7 TP7.1 U1.17 | length 5644.8
  Top Layer w6: U1.17@2421.26,1055.12 2470.03,1055.12 2540.21,1125.3 2540.21,1694.17 2591.45,1745.41 2607.62,1745.41 v1(2610.24,1748.03)
  Top Layer w10: C53.1@594.49,838.58 594.49,839.57 608.19,853.27 609.17,853.27 686.38,930.47 686.38,979.05 J2.16@706.38,999.05 J2.14@806.38,999.05 J2.12@906.38,999.05 J2.10@1006.38,999.05 J2.8@1106.38,999.05 J2.6@1206.38,999.05 J2.4@1306.38,999.05 J2.2@1402.52,999.05 ; J2.2@1406.38,999.05 C42.2@1488.19,999.05 ; C42.2@1488.19,1000 1488.19,1629.92 1535.43,1677.17 1976.38,1677.17 2023.62,1724.41 v4(2023.62,1772.68)
  Bottom Layer w6: J4.7@1190.94,2324.8 1299.71,2324.8 ccw(c1322.83,2374.02) 1345.96,2324.8 1395.67,2324.8 1828.83,1891.64 2576.93,1891.64 2610.24,1858.33 v1(2610.24,1748.03) 2607.62,1745.41 2600.01,1745.41 2599.88,1745.28 2051.02,1745.28 v4(2023.62,1772.68)
  Bottom Layer w10: 1405.51,2318.9 1438.82,2352.2 1438.82,2369.61 1515.75,2446.54 TP7.1@1515.75,2547.24
IPROPI_MCU: J4.8 U3.2 | length 620.5
  Top Layer w10: U3.2@732.28,2039.37 732.28,2019.23 739.09,2019.23 739.09,2008.94 751.97,1996.06 807.09,1996.06 860.02,2048.99 860.02,2091.06 881.38,2112.43 995.3,2112.43 1008,2125.13 1008,2181.79 1035.43,2209.23 1035.43,2283.46 J4.8@1078.74,2326.77
MCU_UARTRXD: J7.8 U3.3 | length 643.3
  Top Layer w6: J7.8@511.81,2468.5 559.06,2515.75 626.77,2515.75 661.42,2481.1 661.42,2342.52 709.65,2294.29 U3.3@709.65,2041.34
MCU_UARTTXD: J7.6 U3.4 | length 456.2
  Top Layer w6: J7.6@614.17,2468.5 614.17,2366.14 684.1,2296.21 684.1,2041.39 U3.4@684.05,2041.34
NetC32_1: C32.1 U6.2 | length 59.9
  Top Layer w10: C32.1@946.89,3441.14 C32.1@947.26,3440.77 ; U6.2@952.81,3494.44 952.81,3435.79 C32.1@953.33,3435.27
NetC47_2: C47.2 J7.1 R47.2 | length 226.1
  Top Layer w6: J7.1@812.4,2568.8 907.57,2568.8 C47.2@913.39,2562.99
  Top Layer w10: R47.2@811.75,2691.24 812.4,2690.6 J7.1@812.4,2568.8
NetC48_2: C48.2 J7.3 R48.2 | length 358.5
  Top Layer w6: v1(877.95,2515.75) C48.2@913.39,2515.75
  Top Layer w10: J7.3@696.85,2574.8 R48.2@712.4,2691.24
  Bottom Layer w6: J7.3@696.85,2574.8 712.4,2559.25 755.91,2515.75 v1(877.95,2515.75)
NetC51_1: C51.1 U4.7 | length 146.5
  Top Layer w10: U4.7@1737.2,3113.19 1737.2,3146.65 1755.91,3165.35 C51.1@1842.52,3165.35
NetC51_2: C51.2 U4.1 | length 116.5
  Top Layer w10: U4.1@1762.8,3288.39 1762.8,3252.95 1775.59,3240.16 C51.2@1838.58,3240.16
NetD1_1: D1.1 R2.2 | length 60.7
  Top Layer w6: R2.2@503.94,1539.37 503.94,1594.49 D1.1@507.87,1598.43
NetD2_1: D2.1 R3.2 | length 138.1
  Top Layer w6: R3.2@1503.74,2126.18 1503.74,2129.72 1590.55,2216.54 D2.1@1602.36,2216.54
NetD3_1: D3.1 R4.2 | length 71.9
  Top Layer w6: R4.2@1984.53,1771.38 1992.83,1771.38 2014.86,1793.4 2047.15,1793.4 D3.1@2047.24,1793.31
NetD5_2: D5.2 R33.1 | length 138.1
  Top Layer w10: R33.1@180.25,3250.24 180.25,3333.59 D5.2@218.94,3372.28
NetD6_2: D6.2 R34.1 | length 122
  Top Layer w10: R34.1@128.28,3250.24 D6.2@128.28,3372.28
NetD7_1: D7.1 R20.2 | length 60.7
  Top Layer w6: D7.1@574.8,1598.43 578.74,1594.49 R20.2@578.74,1539.37
NetF1_2: F1.2 F2.2 J14.2 TP8.1
  other v1: 1929.13,3385.83 2007.87,3385.83 2086.61,3385.83 2165.35,3385.83 2244.09,3385.83 2322.83,3385.83 2401.57,3385.83 2480.32,3385.83 2559.06,3385.83 2637.8,3385.83 2716.54,3385.83 2795.28,3385.83 2874.02,3385.83 2952.76,3385.83 3031.5,3385.83 1968.5,3425.2 2204.72,3425.2 2440.94,3425.2 2519.68,3425.2 2598.43,3425.2 2677.17,3425.2 2755.91,3425.2 2834.65,3425.2 2913.39,3425.2 2992.13,3425.2 3070.87,3425.2 1929.13,3464.57 2007.87,3464.57 2165.35,3464.57 2401.57,3464.57 2480.32,3464.57 2559.06,3464.57 2637.8,3464.57 2716.54,3464.57 2795.28,3464.57 2874.02,3464.57 2952.76,3464.57 3031.5,3464.57 1968.5,3503.94 2204.72,3503.94 2440.94,3503.94 2677.17,3503.94 2755.91,3503.94 2834.65,3503.94 3070.87,3503.94 1929.13,3543.31 2007.87,3543.31 2165.35,3543.31 2401.57,3543.31 2480.32,3543.31 2637.8,3543.31 2716.54,3543.31 2795.28,3543.31 2874.02,3543.31 3031.5,3543.31 1968.5,3582.68 2047.24,3582.68 2125.98,3582.68 2204.72,3582.68 2283.46,3582.68 2362.2,3582.68 2440.94,3582.68 2519.68,3582.68 2598.43,3582.68 2677.17,3582.68 2755.91,3582.68 2834.65,3582.68 2913.39,3582.68 2992.13,3582.68 3070.87,3582.68 1929.13,3622.05 2007.87,3622.05 2086.61,3622.05 2165.35,3622.05 2244.09,3622.05 2322.83,3622.05 2401.57,3622.05 2480.32,3622.05 2559.06,3622.05 2637.8,3622.05 2716.54,3622.05 2795.28,3622.05 2874.02,3622.05 2952.76,3622.05 3031.5,3622.05 1968.5,3661.42 2047.24,3661.42 2125.98,3661.42 2204.72,3661.42 2283.46,3661.42 2362.2,3661.42 2440.94,3661.42 2519.69,3661.42 2598.43,3661.42 2677.17,3661.42 2755.91,3661.42 2834.65,3661.42 2913.39,3661.42 2992.13,3661.42 3070.87,3661.42
NetJ1_2: J1.2 S1.1 | length 195.1
  Top Layer w6: J1.2@216.54,2188.98 316.15,2089.37 316.15,2069.68 S1.1@340.55,2045.28
NetJ2_1: J2.1 R5.2 | length 106.5
  Top Layer w6: J2.1@1406.38,1193.94 1406.38,1296.14 R5.2@1409.45,1299.21
NetJ2_3: J2.3 R6.2 | length 111.1
  Top Layer w6: J2.3@1306.38,1193.94 1306.38,1298.5 R6.2@1311.02,1303.15
NetJ2_5: J2.5 R7.2 | length 110.2
  Top Layer w6: J2.5@1206.38,1193.94 1206.38,1300.87 R7.2@1208.66,1303.15
NetJ2_7: J2.7 R8.2 | length 109.2
  Top Layer w6: R8.2@1106.3,1303.15 1106.38,1303.07 R8.2@1106.38,1302.44 J2.7@1106.38,1193.94
NetJ2_9: J2.9 R9.2 | length 111.5
  Top Layer w6: J2.9@1006.38,1193.94 1006.38,1297.72 R9.2@1011.81,1303.15
NetJ2_11: J2.11 R10.2 | length 110.5
  Top Layer w6: J2.11@906.38,1193.94 906.38,1300.08 R10.2@909.45,1303.15
NetJ2_13: J2.13 R11.2 | length 107.9
  Top Layer w6: J2.13@803.15,1196.85 807.09,1200.79 R11.2@807.09,1303.15
NetJ2_15: J2.15 R12.2 | length 110.2
  Top Layer w6: J2.15@706.38,1193.94 706.38,1300.87 R12.2@708.66,1303.15
NetJ4_12: J4.12 R28.1 | length 114
  Top Layer w10: R28.1@982.28,2047.24 996.06,2047.24 J4.12@1066.93,2118.11
NetJ4_14: J4.14 R27.1 | length 113.4
  Top Layer w10: R27.1@984.25,1976.38 1019.68,1976.38 J4.14@1074.8,2031.5
NetJ4_16: J4.16 R26.1 | length 106.2
  Top Layer w10: R26.1@982.28,1905.51 1055.12,1905.51 J4.16@1078.74,1929.13
NetJ4_18: J4.18 R25.1 | length 96.5
  Top Layer w10: R25.1@978.35,1826.77 J4.18@1074.8,1826.77
NetJ5_2: J5.2 R42.2 | length 106.5
  Top Layer w10: R42.2@789.85,3748.33 789.85,3810.41 814.02,3834.58 J5.2@814.02,3844.87
NetJ5_4: J5.4 R41.2 | length 110.8
  Top Layer w10: J5.4@714.02,3844.87 748.47,3810.41 R41.2@748.47,3748.33
NetJ6_1: J6.1 L2.1 | length 129.4
  Top Layer w15: L2.1@1030.48,3811.43 1084.25,3811.43 1102,3829.18 J6.1@1102,3879.7
NetJ6_5: J6.5 L3.1 | length 75.2
  Top Layer w15: J6.5@1204.36,3879.7 1204.36,3835.82 L3.1@1226.54,3813.64
NetJ7_5: J7.5 R49.2 | length 122.9
  Top Layer w10: J7.5@612.4,2568.8 612.4,2690.39 R49.2@613.32,2691.3
NetJ7_7: J7.7 R50.2 | length 122.7
  Top Layer w10: J7.7@512.4,2568.8 512.4,2690.61 R50.2@513.04,2691.24
NetJ10_1: J10.1 R13.1 | length 110.4
  Top Layer w6: R13.1@511.81,1303.15 514.57,1300.39 J10.1@514.57,1193.94
NetJ10_2: J10.2 J10.4 J10.6 J10.8 J10.10 R14.2 | length 1945.4
  Top Layer w6: J10.10@116.38,999.05 J10.8@214.57,999.05 J10.6@314.57,999.05 J10.4@414.57,999.05 J10.2@514.57,999.05 514.8,999.05 J10.2@515.75,1000 ; J10.2@516.38,999.05 581.73,999.05 614.17,1031.5 v1(614.17,1236.22) ; v1(1424.33,1940.08) 1451.41,1967.15 R14.2@1458.05,1967.15
  Top Layer w10: J10.2@519.68,946.5 J10.2@519.68,972.44
  Bottom Layer w6: v1(614.17,1236.22) 614.17,1318.9 1040.86,1745.58 cw(c1078.74,1729.92) 1063.08,1767.8 1084.63,1789.35 ccw(c1078.74,1829.92) 1119.31,1824.03 1140.86,1845.58 cw(c1178.74,1829.92) 1163.08,1867.8 1184.63,1889.35 ccw(c1178.74,1929.92) 1219.31,1924.03 1235.35,1940.08 v1(1424.33,1940.08)
NetJ10_3: J10.3 R53.2 | length 113.6
  Top Layer w6: R53.2@413.39,1307.09 414.57,1305.91 J10.3@414.57,1193.94
NetJ10_5: J10.5 R57.2 | length 109.4
  Top Layer w6: J10.5@314.57,1193.94 314.57,1302.76 R57.2@314.96,1303.15
NetJ10_7: J10.7 R61.2 | length 110
  Top Layer w6: R61.2@212.6,1303.15 214.57,1301.18 J10.7@214.57,1193.94
NetJ10_9: J10.9 R64.2 | length 110.7
  Top Layer w6: J10.9@114.57,1193.94 114.57,1299.61 R64.2@118.11,1303.15
NetJ11_1: J11.1 R15.1 | length 126.3
  Top Layer w6: J11.1@1467.87,470.08 1467.87,589.92 R15.1@1472.44,594.49
NetJ11_2: J11.2 J11.4 J11.6 J11.8 J11.10 R16.2 | length 2224.8
  Top Layer w6: v1(1433.07,1748.03) R16.2@1456.69,1771.65 ; J11.2@1467.87,278.77 1535.43,346.32 v1(1535.43,519.69)
  Top Layer w10: J11.10@1067.87,278.77 J11.2@1467.87,278.77
  Bottom Layer w6: v1(1433.07,1748.03) 1370.15,1748.03 1368.24,1748.03 1366.67,1749.14 cw(c1370.15,1754.03) 1365.48,1750.27 ccw(c1322.83,1716.54) 1272.66,1737.49 1259.84,1724.67 1259.84,791.34 v1@1535.43,515.75
NetJ11_3: J11.3 R54.2 | length 128.7
  Top Layer w10: J11.3@1367.87,473.65 R54.2@1367.87,602.36
NetJ11_5: J11.5 R58.2 | length 129.7
  Top Layer w10: J11.5@1267.87,473.65 1267.87,599.94 R58.2@1270.29,602.36
NetJ11_7: J11.7 R62.2 | length 128.7
  Top Layer w10: J11.7@1167.87,473.65 R62.2@1167.87,602.36
NetJ11_9: J11.9 R65.2 | length 129.6
  Top Layer w10: J11.9@1067.87,473.65 1067.87,600.31 R65.2@1069.92,602.36
NetJ12_1: J12.1 R17.1 | length 128.7
  Top Layer w10: J12.1@891.99,473.65 R17.1@891.99,602.36
NetJ12_2: J12.2 J12.4 J12.6 J12.8 J12.10 R39.2 | length 2399
  Top Layer w6: J12.10@491.99,278.77 691.99,278.77 890.53,278.77 J12.2@893.7,275.59 ; J12.2@891.99,278.77 940.18,278.77 980.32,318.9 v1(980.32,531.5) ; v1(1374.02,1803.15) 1437.72,1866.85 1452.05,1866.85 R39.2@1456.69,1862.2
  Bottom Layer w6: v1(980.32,531.5) 985.99,531.5 1240.16,785.66 1240.16,1822.83 1267.72,1850.39 1278,1850.39 1279.76,1848.64 1280.01,1848.38 1280.01,1847.82 1284.39,1843.44 1300.31,1827.52 1349.65,1827.52 v1(1374.02,1803.15)
NetJ12_3: J12.3 R55.2 | length 129.2
  Top Layer w10: J12.3@791.99,473.65 791.99,601.15 R55.2@793.2,602.36
NetJ12_5: J12.5 R59.2 | length 128.7
  Top Layer w10: J12.5@691.99,473.65 R59.2@691.99,602.36
NetJ12_7: J12.7 R63.2 | length 128.7
  Top Layer w10: J12.7@591.99,473.65 R63.2@591.99,602.36
NetJ12_9: J12.9 R66.2 | length 116.6
  Top Layer w6: J12.9@491.99,470.08 491.99,586.48 R66.2@492.13,586.61
NetJ13_1: J13.1 R23.1 | length 80.4
  Top Layer w10: J13.1@263.78,527.56 267.72,531.5 R23.1@267.72,606.3
NetJ13_2: J13.2 J13.4 R52.2 | length 2654
  Top Layer w6: 113.01,277.78 312.77,277.78 314.96,275.59 ; 313.01,277.78 360.46,277.78 401.57,318.9 v1(401.57,511.81) ; v1(1433.07,2035.43) 1440.94,2035.43 R52.2@1464.57,2059.06
  Bottom Layer w6: v1(401.57,511.81) 401.57,1185.04 1037.75,1821.21 1037.75,1846.9 1079.78,1888.93 1095.72,1888.93 1119.73,1912.94 1119.73,1928.88 1163.29,1972.44 1177.17,1972.44 1193.65,1988.93 1204.29,1988.93 1231.11,2015.75 1265.62,2015.75 1296.38,1985 1334.12,1985 ccw(c1334.12,1991) 1335.02,1985.06 1336.85,1985.34 cw(c1337.74,1979.41) 1337.02,1985.36 ccw(c1330.71,2039.37) 1384.35,2030.46 cw(c1390.26,2029.43) 1386.8,2034.34 1388.36,2035.43 v1(1433.07,2035.43)
NetQ1_4: Q1.4 U4.2 U4.6 | length 662.1
  Top Layer w10: U4.6@1711.61,3113.19 1711.61,3152.56 1763.78,3204.72 ; U4.2@1737.2,3288.39 1737.2,3231.3 1763.78,3204.72 ; Q1.4@2015.35,2988.19 1905.51,2988.19 1889.76,3003.94 1889.76,3196.85 1881.89,3204.72 1763.78,3204.72
nFAULT: J4.9 R1.1 R3.1 TP10.1 U1.18 | length 3144.6
  Top Layer w6: v1(1437.01,2188.98) 1440.94,2188.98 R3.1@1464.57,2165.35 ; R3.1@1464.76,2165.16 1535.43,2235.82 R1.1@1535.43,2240.16 ; U1.18@2428.07,1074.8 2470.1,1074.8 2526.34,1131.05 2526.34,1720.17 v1(2572.25,1766.08)
  Top Layer w10: J4.9@1196.85,2224.41 1225.31,2252.87 1225.31,2256.18 1243.19,2274.06 1243.19,2551.26 1322.83,2630.91 TP10.1@1322.83,2708.66
  Bottom Layer w6: J4.9@1173.23,2228.35 1185.04,2216.54 1252.66,2216.54 1253.73,2216.54 1254.73,2216.9 ccw(c1252.66,2222.54) 1258.39,2220.76 cw(c1321.48,2201.42) 1386.08,2187.95 ccw(c1391.96,2186.77) 1390.05,2181.08 1390.98,2180.77 1391.96,2180.77 1428.8,2180.77 v1(1437.01,2188.98) 1774.56,1851.43 2150.31,1851.43 2172.8,1828.94 2556.89,1828.94 2574.02,1811.8 2574.02,1770.87 v1@2570.87,1767.72
nFAULT_MCU: J4.10 U3.16 | length 938.2
  Top Layer w6: U3.16@453.74,1809.06 453.74,1890.75 511.81,1948.82 832.45,1948.82 865.95,1982.32 865.95,2031.18 875.89,2041.12 875.89,2084.49 887.95,2096.55 1001.87,2096.55 1023.87,2118.55 1023.87,2175.22 1042.6,2193.94 1066.93,2193.94 J4.10@1066.93,2224.41
nSCS/DIAG: J4.17 R16.1 TP14.1 U1.2 | length 2287.7
  Top Layer w6: R16.1@1502.59,1737.57 1524.97,1737.57 v1(1535.43,1748.03) ; v1(2165.58,1865.45) 2165.58,1864.17 2229.57,1800.19 2229.57,1464.05 2229.19,1463.67 2229.19,1188.13 2291.34,1125.98 U1.2@2291.34,1094.49
  Top Layer w10: J4.17@1192.91,1822.83 1266.46,1896.38 1266.46,1905.24 1321.85,1960.63 ; TP14.1@1326.77,2035.43 1326.77,1965.55 1321.85,1960.63 ; v4(1389.76,1913.39) 1342.52,1960.63 1321.85,1960.63
  Signal Layer 2 w10: v1(2073.67,1703.69) 2074.1,1704.12 2074.1,1876.6 2098.87,1901.37 2129.67,1901.37 v1(2165.58,1865.45)
  Bottom Layer w6: v4@1393.7,1909.45 1393.7,1889.76 v1(1535.43,1748.03) ; v1@1539.37,1748.03 1539.37,1744.09 1587.96,1695.5 2063.65,1695.5 2071.84,1703.69 v1(2073.67,1703.69)
nSCS_MCU: R25.2 R68.2 U3.10 | length 623.8
  Top Layer w6: U3.10@530.51,2047.24 530.51,2121.06 R68.2@535.43,2125.98 ; v1(531.5,1980.32) U3.10@531.5,2047.24 ; R25.2@917.32,1826.77 R25.2@926.18,1835.63
  Top Layer w10: v1(866.14,1826.77) 917.32,1826.77 R25.2@921.26,1826.77
  Bottom Layer w6: v1(531.5,1980.32) 531.5,1962.83 655.74,1838.58 854.33,1838.58 v1(866.14,1826.77)
nSLEEP: J4.5 R22.2 TP4.1 | length 3899.3
  Top Layer w10: R22.2@2677.17,1145.67 2678.23,1145.67 2685.04,1152.48 v1(2685.04,1200.79)
  Bottom Layer w6: 1456.69,2362.2 1913.39,1905.51 2582.68,1905.51 2775.59,1712.6 3102.36,1712.6 3128.54,1686.42 3128.54,1171.84 3062.99,1106.3 2748.03,1106.3 2685.04,1169.29 v1(2685.04,1200.79)
  Bottom Layer w10: J4.5@1178.74,2429.92 1315.58,2429.92 cw(c1322.83,2374.02) 1330.09,2429.92 1339.37,2429.92 1459.44,2549.99 cw(c1515.75,2547.24) 1512.08,2603.5 1513.47,2603.59 cw(c1514.16,2593.62) 1514.16,2603.62 1519.68,2603.62 ; 1456.69,2362.2 1539.1,2444.61 1539.1,2494 1542.03,2496.93 1542.99,2497.89 ccw(c1515.75,2547.24) 1571.82,2553.08 ccw(c1515.75,2547.24) 1554.28,2588.39 cw(c1561.17,2595.65) 1553.91,2588.77 ccw(c1519.68,2556.76) 1519.68,2603.62 ; TP4.1@1519.68,2712.6 1519.68,2603.62
nSLEEP/VDD: C41.1 R19.1 R22.1 TP18.1 U1.16 | length 2043.5
  Top Layer w6: U1.16@2421.53,1035.71 2492.01,1035.71 2535.32,1079.01 C41.1@2606.03,1079.01 ; C41.1@2606.3,1078.74 2673.23,1078.74 R22.1@2677.17,1074.8 ; R22.1@2677.17,1074.8 2685.11,1082.68 v1(2744.09,1082.68)
  Top Layer w10: TP18.1@2952.76,2255.91 2980.31,2228.35 3107.63,2228.35 3125.08,2210.9 3125.08,2047.12 3130.94,2041.26 3138.86,2041.26 3144.41,2035.71 R19.1@3144.41,2027.56 ; v5(3137.8,1976.38) R19.1@3137.8,2015.75
  Bottom Layer w10: v1(2744.09,1082.68) 3102.36,1082.68 3144.41,1124.72 3144.41,1965.98 3137.8,1972.59 v5(3137.8,1976.38)
nSLEEP_MCU: J4.6 U3.17 | length 1122.3
  Top Layer w6: U3.17@479.33,1809.06 479.33,1888.78 525.5,1934.94 844.39,1934.94 879.83,1970.38 879.83,2025.43 889.76,2035.37 889.76,2078.74 893.7,2082.68 1009.05,2082.68 1037.75,2111.38 1037.75,2159.8 v1(1051.18,2173.23)
  Bottom Layer w6: v1(1051.18,2173.23) 1039.08,2219.56 cw(c1078.74,2229.92) 1037.75,2229.92 1037.75,2329.92 cw(c1078.74,2329.92) 1041.35,2346.72 J4.6@1078.74,2429.92
OUT1: C3.1 C39.2 J8.1 TP5.1 U1.7 U1.8
  other v1: 1633,116 1708,116 1783,116 1858,116 1933,116 2008,116 2083,116 2158,116 1670.5,191 1745.5,191 1820.5,191 1895.5,191 1970.5,191 2045.5,191 2120.5,191 1633,266 1708,266 1783,266 1858,266 1933,266 2008,266 2083,266 2158,266 1745.5,341 1820.5,341 1970.5,341 2045.5,341 2120.5,341 1633,416 1708,416 1783,416 1858,416 1933,416 2008,416 2083,416 2158,416 1745.5,491 1820.5,491 1895.5,491 1970.5,491 2045.5,491 2120.5,491 1783,566 1933,566 2008,566 2083,566 2158,566 1670.5,641 1745.5,641 1820.5,641 1895.5,641 1970.5,641 2045.5,641 2120.5,641 1633,716 1708,716 1783,716 1858,716 1933,716 2008,716 2083,716 1670.5,791 1745.5,791 1820.5,791 1895.5,791 1970.5,791 2045.5,791 2120.5,791 1633,866 1708,866 1858,866 1933,866 2008,866 2083,866 2158,866 1670.5,941 1895.5,941 1970.5,941 2045.5,941 2120.5,941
